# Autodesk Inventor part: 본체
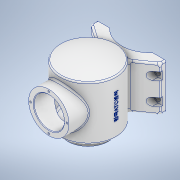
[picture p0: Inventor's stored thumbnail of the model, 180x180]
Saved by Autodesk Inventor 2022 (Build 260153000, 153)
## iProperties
Created: 2023-04
Part Number: 본체
Material: 알루미늄 6061
Document SubType Name: Modeling
Designer: Admin
Density: 2.7 g/cm^3
Appearance: 알루미늄 - 평지
Mass: 1316.24 g
Surface Area: 1081.4 cm^2
Volume: 487.496 cm^3
Author: Admin
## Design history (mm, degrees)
sketch "스케치1"
  geometry: L1 (-62, 40)-(62, 40); L2 (62, 40)-(62, -40); L3 (62, -40)-(-62, -40); L4 (-62, -40)-(-62, 40); L5 (-86.8, 0)-(86.8, 0) reference; L6 (0, -56)-(0, 56) reference; 1 further point
  constraints: 8 end point, 2 parallel, 1 horizontal, 1 perpendicular, 2 other
  dimensions: "d0" = 124 distance of L1.start L1.end; "d1" = 80 distance of L3.end L1.start
extrude "돌출1" new body sketch "스케치1" stored distance "d2" = 10; taper "d3" = 0 deg
sketch "스케치2"
  geometry: 1 further point
sketch "스케치3"
  geometry: L1 (40, -5)-(-40, -5) reference; L2 (-40, -5)-(-40, 5) reference; L3 (-133.479, 72)-(264.868, 72); L4 (-60, 72)-(-48, 72); L5 (-48, 72)-(-48, 108); L6 (-48, 108)-(-60, 108); L7 (-60, 108)-(-60, 72); L8 (-48, 72)-(-36, 72); L9 (-36, 122)-(-48, 122); L10 (-48, 122)-(-48, 72); L11 (-36, 72)-(36, 72); L12 (36, 72)-(48.336, 72); L13 (48.336, 72)-(48.336, 122); L14 (48.336, 122)-(36, 122); L15 (0, -30.534)-(0, 148.205) reference; L16 (-36, 122)-(36, 122); A1 r 113 centre (-53, 72) between (60, 72) and (48.336, 122); 3 further points
  constraints: 26 end point, 5 horizontal, 5 parallel, 3 point on line, 2 perpendicular, 2 point on circle, 1 centre point
  dimensions: "d16" = 113 radius of A1; "d17" = 20 distance from line of L2 L4.start; "d18" = 120 horizontal distance of L6.end A1.start; "d19" = 108 horizontal distance of A1.start L9.end; "d21" = 72 diameter of L6.end L3; "d22" = 100 diameter of L9.end L3; "d24" = 100 diameter of L13.end L3; "d28" = 154 diameter of L1 L3
revolve "회전1" sketch "스케치3" stored, may be unused: angle "d25" = 90 deg
node "작업 평면1"
sketch "스케치5"
  geometry: L1 (36, -60)-(-36, -60) reference; L2 (0, -84)-(0, 84) reference; C1 r 36 at (0, 2); 1 further point
  constraints: 1 centre point, 1 point on line
  dimensions: "d109" = 62 distance from line of L1 C1.centre; "d110" = 72 diameter of C1
extrude "돌출2" join sketch "스케치5" stored distance "d31" = 142; taper "d32" = 0 deg
sketch "스케치10"
  geometry: L1 (-85.453, 72)-(94.043, 72); L2 (-40, -5)-(40, -5) reference; L3 (-60, 36)-(-60, 108) reference; L4 (-60, 72)-(-41, 72); L5 (-41, 72)-(-41, 99); L6 (-41, 99)-(-60, 99); L7 (-60, 99)-(-60, 72); L8 (-41, 72)-(44.499, 72); L9 (44.499, 72)-(44.499, 115); L10 (44.499, 115)-(-41, 115); L11 (-41, 115)-(-41, 72); A1 r 113 centre (-53, 72) between (48.336, 22) and (48.336, 122) reference; A2 r 113 centre (-60, 72) between (53, 72) and (44.499, 115); 3 further points
  constraints: 18 end point, 4 parallel, 3 horizontal, 2 perpendicular, 2 point on circle, 2 point on line, 1 centre point, 1 midpoint
  dimensions: "d40" = 77 distance between parallel lines of L2 L1; "d42" = 54 diameter of L6.end L1; "d43" = 86 diameter of L10.end L1; "d45" = 19 distance of L5.end L6.end; "d48" = 226 diameter of A2; "d49" = 7 distance of A1.centre A2.centre
revolve "회전2" sketch "스케치10" stored, may be unused: angle "d50" = 90 deg
sketch "스케치22"
  geometry: C1 r 27 at (0, 0); C2 r 36 at (0, 0) reference; 1 further point
  constraints: 1 centre point, 1 coincident
  dimensions: "d112" = 54 diameter of C1
extrude "돌출8" cut sketch "스케치22" stored distance "d113" = 10; taper "d114" = 0 deg
sketch "스케치23"
  geometry: C1 r 27 at (0, 0) reference; C2 r 36 at (0, 0) reference; 5 further points
  constraints: 1 horizontal alignment, 5 other
  dimensions: "d115" = 32.5 distance of C1.centre point (-32.5, 0); "d118" = 360 deg dimension on C2.centre point (-32.5, 0) (derived)
hole "구멍4" sketch "스케치23" at (-32.5, 0), (0, -32.5), (32.5, 0), (0, 32.5) diameter "d120" = 3.242; stored, may be unused: countersink angle "d124" = 90 deg, drill point angle "d126" = 118 deg; dims "d121" = 8, "d122" = 4, "d123" = 2, "d125" = 10
sketch "스케치13"
  geometry: L1 (0, -102.4)-(0, 75.4) reference; C1 r 27 at (0, 0) reference; C2 r 36 at (0, 0) reference; 5 further points
  constraints: 1 point on line, 5 other
  dimensions: "d66" = 32.5 distance of C1.centre point (0, 32.5); "d69" = 360 deg dimension on C2.centre point (0, 32.5) (derived)
hole "구멍2" sketch "스케치13" at (0, 32.5), (-32.5, 0), (0, -32.5), (32.5, 0) diameter "d71" = 3.242; stored, may be unused: countersink angle "d75" = 90 deg, drill point angle "d77" = 118 deg; dims "d72" = 8, "d73" = 4, "d74" = 2, "d76" = 10
sketch "스케치14"
  geometry: L1 (62, 40)-(-62, 40) reference; L2 (-62, -40)-(62, -40) reference; L3 (-10, 40)-(10, 40); L4 (10, 40)-(10, -40); L5 (10, -40)-(-10, -40); L6 (-10, -40)-(-10, 40); L7 (0, -84)-(0, 84) reference; 1 further point
  constraints: 8 end point, 2 parallel, 2 point on line, 1 horizontal, 1 perpendicular, 1 other
  dimensions: "d78" = 20 distance between parallel lines of L6 L4
extrude "돌출5" join sketch "스케치14" stored distance "d79" = 10; taper "d80" = 0 deg
sketch "스케치15"
  geometry: L1 (-62, 5)-(-10, 5) reference; L2 (-62, 5)-(-26.694, 29.722); L3 (-62, -5)-(-62, 5) reference; 2 further points
  constraints: 2 end point, 2 other
  dimensions: "d81" = 55 deg angle of L3 L2
feature "리브1" sketch "스케치15" dims "d82" = 1, "d83" = 80, "d84" = 0, "d85" = 0, "d86" = 1, "d87" = 1
sketch "스케치16"
  geometry: L1 (124, 0)-(0, 0) reference; L2 (62, -12.727)-(62, 19.916); L3 (0, 10)-(0, 0) reference; L4 (62, 17)-(82.89, 17); L5 (23.5, 0)-(100.5, 0); A1 r 52.096 centre (62, -35.096) between (100.5, 0) and (23.5, 0); 1 further point
  constraints: 6 end point, 3 point on circle, 3 point on line, 1 centre point, 1 collinear, 1 horizontal, 1 symmetric about line, 1 tangent, 1 vertical
  dimensions: "d88" = 77 distance of L5.end L5.start; "d89" = 62 distance between parallel lines of L3 L2; "d90" = 17 distance between parallel lines of L1 L4
extrude "돌출6" cut sketch "스케치16" extent not by distance; stored distance "d91" = 0; taper "d92" = 0 deg
sketch "스케치18"
  geometry: L1 (62, -40)-(62, 40) reference; L2 (62, 40)-(38.5, 40) reference; 3 further points
  constraints: 1 vertical alignment
  dimensions: "d95" = 40 distance of point (54, -20) point (54, 20); "d96" = 8 distance from line of L1 point (54, 20); "d97" = 20 distance from line of L2 point (54, 20)
hole "구멍3" sketch "스케치18" at (54, 20), (54, -20) diameter "d98" = 9; stored, may be unused: countersink angle "d102" = 90 deg, drill point angle "d104" = 0 deg; dims "d99" = 6, "d100" = 4, "d101" = 2, "d103" = 6
sketch "스케치20"
  geometry: L1 (8, 20)-(8, -60) reference; L2 (8, -7)-(0, -7); L3 (8, 7)-(0, 7); L4 (8, 7)-(8, -7); C1 r 4.5 at (0, 0) reference; A1 r 7 centre (0, 0) between (0, 7) and (0, -7); 1 further point
  constraints: 6 end point, 2 horizontal, 2 point on circle, 2 point on line, 2 tangent, 1 centre point, 1 coincident
  dimensions: "d106" = 14 diameter of A1
extrude "돌출7" cut sketch "스케치20" distance "d107" = 20; taper "d108" = 0 deg
node "작업 평면2"
sketch "스케치21"
  geometry: L1 (-60.168, -36)-(-60.168, 36) reference; L2 (39.832, -42.278)-(39.832, -42.278) reference; L3 (39.832, -42.278)-(-40.168, -42.278) reference; L4 (-40.168, -42.278)-(-40.168, -42.278) reference; L5 (-40.168, -42.278)-(39.832, -42.278) reference; L6 (48.168, -50)-(48.168, 50) reference; L7 (-48.168, -50)-(-48.168, 50) reference; L8 (39.832, -77)-(-40.168, -77) reference; 3 further points
  constraints: 1 other
  dimensions: "d127" = 62 distance from line of L1 point (1.832, 0); "d128" = 77 distance from line of L8 point (1.832, 0)
feature "엠보싱1" sketch "스케치21" dims "d0" = 124, "d1" = 80, "d16" = 113, "d17" = 20, "d18" = 120, "d19" = 108, "d21" = 72, "d22" = 100, "d24" = 100, "d28" = 154, "d129" = 0.5, "d130" = 0
fillet "모깎기1" dims "d131" = 3
chamfer "모따기1" distance "d132" = 1; stored, may be unused: second distance "d133" = 2, angle "d134" = 45 deg
fillet "모깎기2" dims "d135" = 3
node "솔리드1"
mirror "미러2"
mirror "미러3"
mirror "미러4"
mirror "미러5"
node "투영된 루프7"
node "투영된 루프10"
node "투영된 루프11"
node "투영된 루프12"
feature "A9D066F2-1C7D-4E18-AEED-F7BC21143FA4" dims "d98" = 9, "d99" = 6, "d100" = 4, "d101" = 2, "d102" = 90 deg, "d103" = 6, "d104" = 0
other parameters: "d29" = 142, "d44" = 113
